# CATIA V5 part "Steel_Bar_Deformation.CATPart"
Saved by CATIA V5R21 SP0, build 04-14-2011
Part number: Part1
Material "Steel": density 7860 kg/m3, Young's modulus 2e+11 Pa, Poisson ratio 0.266, thermal expansion 1.17e-05 1/K
Bounding box of the stored display mesh (mm): x 0 to 500, y -25 to 225, z -4 to 54
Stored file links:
  G:\CATIA\Analysis\Steel_Bar_Deformation.CATPart
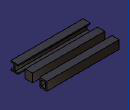
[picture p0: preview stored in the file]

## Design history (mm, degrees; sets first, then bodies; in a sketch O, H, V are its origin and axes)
AxisSystem1: origin (0, 0, 0), X (1, 0, 0), Y (0, 1, 0), Z (0, 0, 1)
Body1 (main body), material "Steel"
  Sketch1 on YZ plane of AxisSystem1, origin (0, 0, 0), H (0, 1, 0), V (0, 0, 1)
    line L1 (0, 0) -> (0, 50)
    line L2 (-25, 50) -> (25, 50)
    point P2 (-25, 50)
    point P3 (25, 50)
    line L3 (-25, 0) -> (25, 0)
    length L1 = 50
    length L2 = 50
    distance L2 H = 50
    length L3 = 50
    vertical: L1 V
    horizontal: L2 H, L3 H
    symmetry: P2 P3 L1
    midpoint: L3 O
  Pad1: profile Sketch1, direction (1, 0, 0), length 500, thin wall 8
  Sketch2 on YZ plane of AxisSystem1, origin (0, 0, 0), H (0, 1, 0), V (0, 0, 1)
    point P1 (100, 25)
    line L1 (125, 54) -> (125, -4)
    line L2 (125, -4) -> (75, -4)
    line L3 (75, -4) -> (75, 54)
    line L4 (75, 54) -> (125, 54)
    reference projected line E1 (-25, -4) -> (25, -4) from edge [face of Pad1 | end face of Pad1]
    reference projected line E2 through (0, 0) direction (0, 1) from edge [ZX plane of AxisSystem1 | YZ plane of AxisSystem1]
    length L1 = 58
    length L4 = 50
    distance E2 L3 = 75
    vertical: L1 V, L3 V
    horizontal: L2 H, L4 H
    equidistance: L1 L3 P1, L2 L4 P1
    coincidence: L2 E1
  Pad2: profile Sketch2, direction (1, 0, 0), length 500
  Sketch3 on YZ plane of AxisSystem1, origin (0, 0, 0), H (0, 1, 0), V (0, 0, 1)
    line L1 (185, 44) -> (185, 6)
    line L2 (185, 6) -> (215, 6)
    line L3 (215, 6) -> (215, 44)
    line L4 (215, 44) -> (185, 44)
    line L5 (175, 54) -> (225, 54)
    line L6 (225, 54) -> (225, -4)
    line L7 (225, -4) -> (175, -4)
    line L8 (175, -4) -> (175, 54)
    point P8 (175, -4)
    reference projected line E1 (-25, -4) -> (25, -4) from edge [face of Pad1 | end face of Pad1]
    reference projected line E2 (-25, 54) -> (25, 54) from edge [end face of Pad1 | face of Pad1]
    reference projected point E3 (125, -4) from vertex [face of Pad2 from Sketch2.L1 | face of Pad2 from Sketch2.L2 | end face of Pad2]
    length L3 = 38
    length L4 = 30
    distance E3 P8 = 50
    length L7 = 50
    distance L1 L8 = 10
    distance L4 L5 = 10
    vertical: L1 V, L3 V, L6 V, L8 V
    horizontal: L2 H, L4 H, L5 H, L7 H
    coincidence: L7 E1, L5 E2
  Pad3: profile Sketch3, direction (1, 0, 0), length 500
